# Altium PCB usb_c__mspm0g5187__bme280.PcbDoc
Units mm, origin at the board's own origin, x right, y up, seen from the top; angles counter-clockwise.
Board outline 64 x 33 mm, 2 copper layers (Top, Bottom), stack 0 mm thick; 27 components, 19 nets, 159 pads, 67 vias.
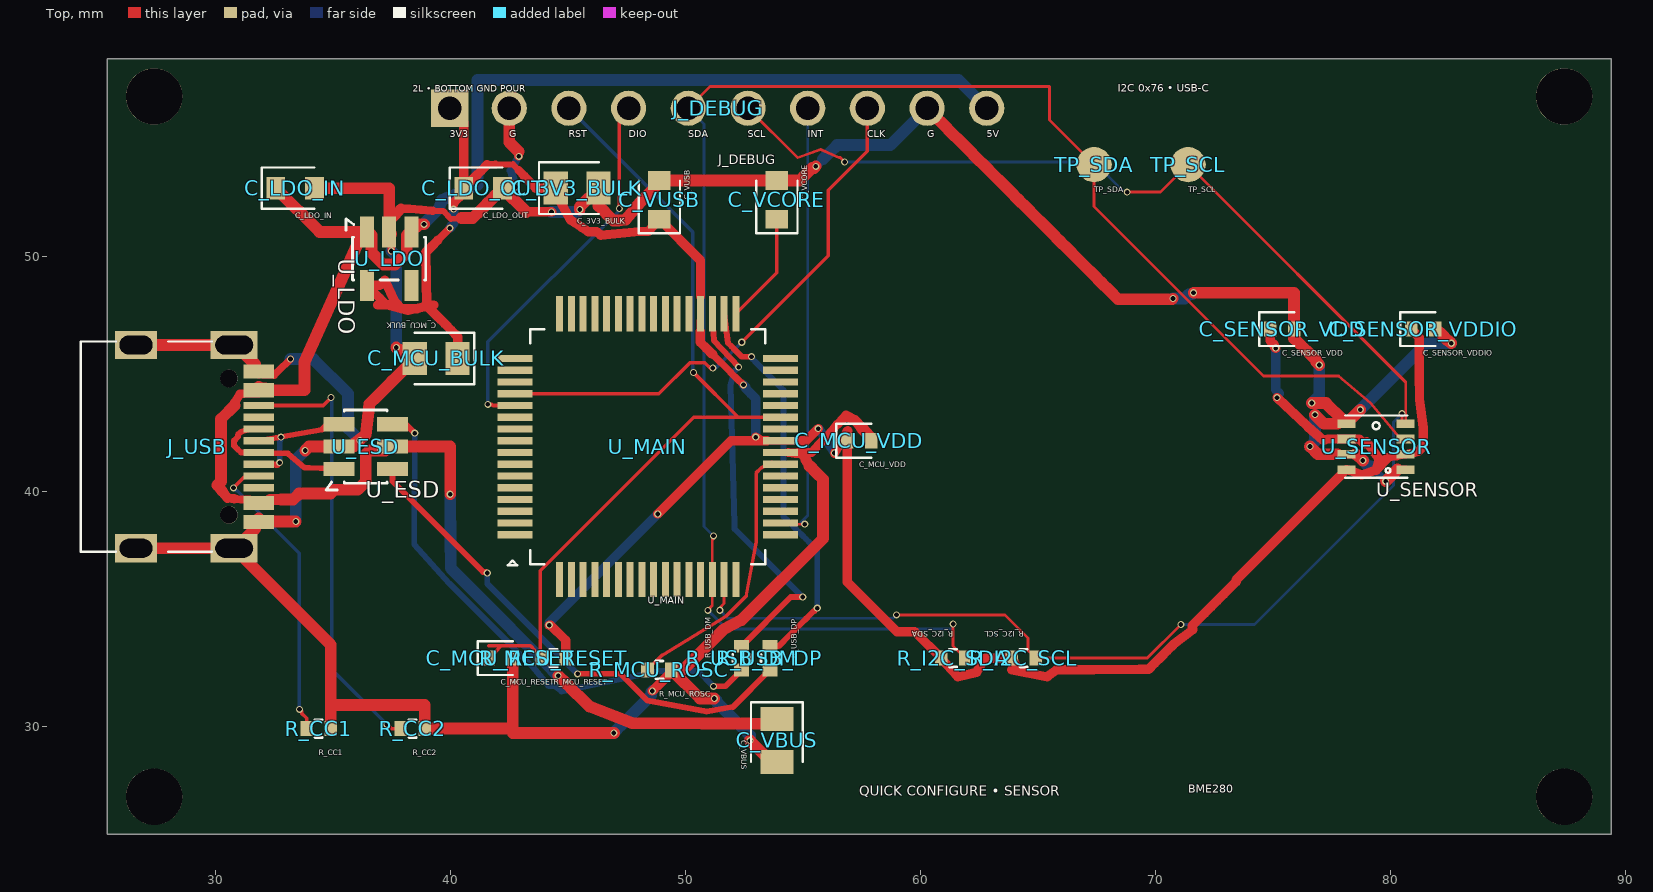
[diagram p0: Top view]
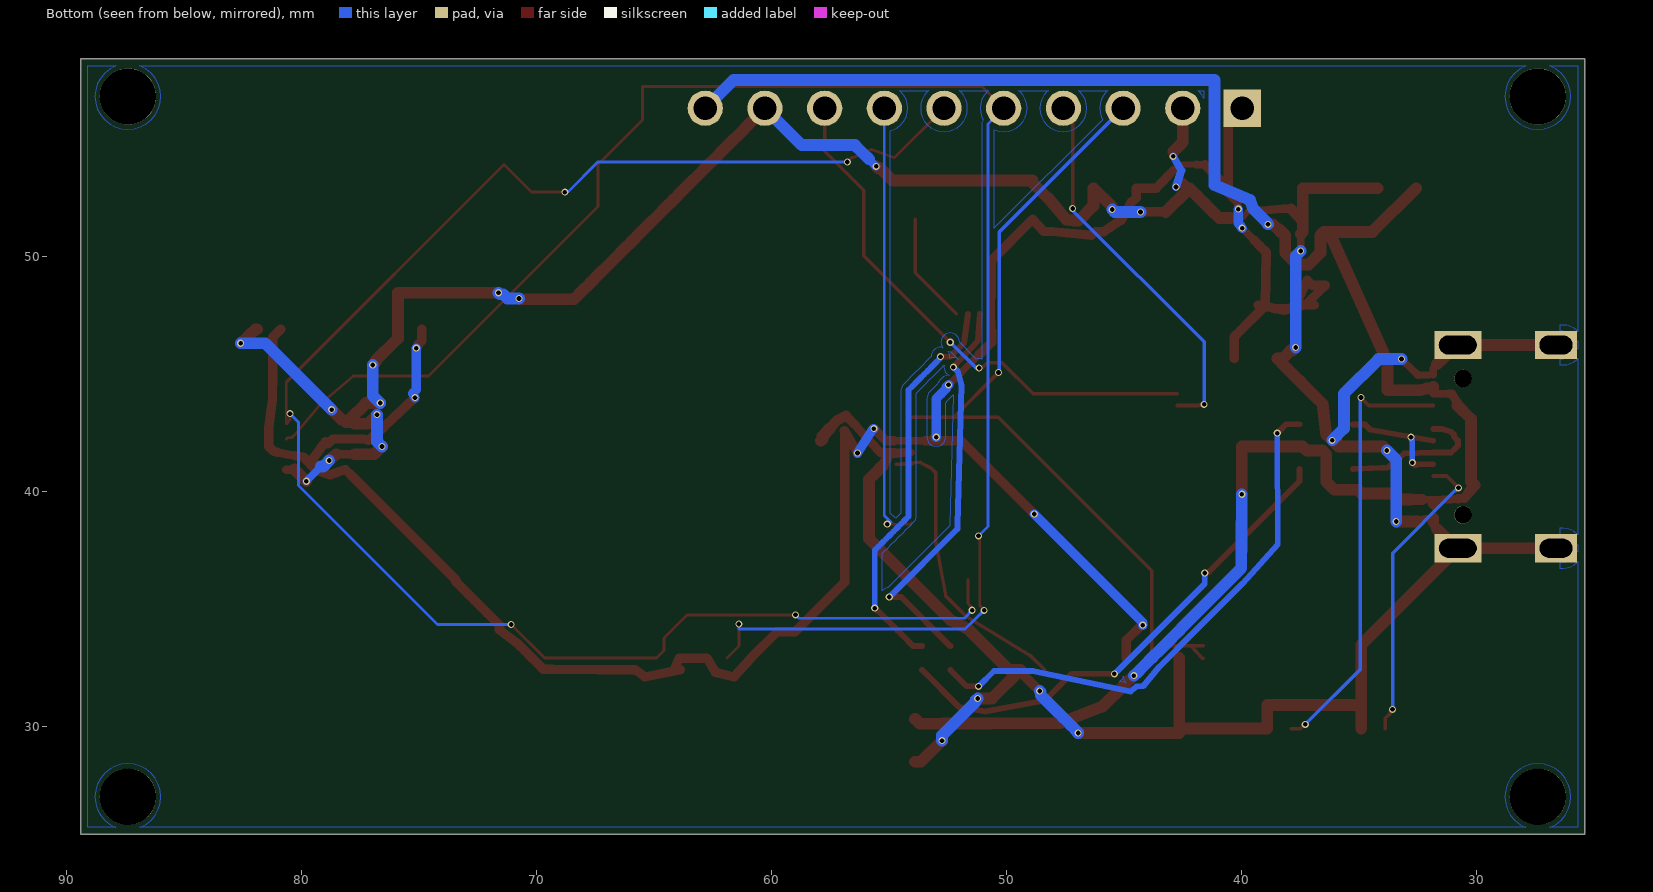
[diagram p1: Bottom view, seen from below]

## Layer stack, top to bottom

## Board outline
25.4,58.4 89.4,58.4 89.4,25.4 25.4,25.4

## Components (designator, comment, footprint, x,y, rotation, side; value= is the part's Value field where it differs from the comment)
C_3V3_BULK "" TSCIRCUIT-2.8500x1.4000mm 45.4,52.9 r0 top
C_LDO_IN "" TSCIRCUIT-2.4500x0.9500mm 33.4,52.9 r0 top
C_LDO_OUT "" TSCIRCUIT-2.4500x0.9500mm 41.4,52.9 r0 top
C_MCU_BULK "" TSCIRCUIT-2.8500x1.4000mm 39.4,45.65 r180 top
C_MCU_RESET "" TSCIRCUIT-1.5600x0.6400mm 42.15,32.9 r0 top
C_MCU_VDD "" TSCIRCUIT-1.5600x0.6400mm 57.4,42.15 r0 top
C_SENSOR_VDD "" TSCIRCUIT-1.5600x0.6400mm 75.4,46.9 r0 top
C_SENSOR_VDDIO "" TSCIRCUIT-1.5600x0.6400mm 81.4,46.9 r0 top
C_VBUS "" TSCIRCUIT-1.4000x2.8500mm 53.9,29.4 r270 top
C_VCORE "" TSCIRCUIT-0.9500x2.4500mm 53.9,52.4 r90 top
C_VUSB "" TSCIRCUIT-0.9500x2.4500mm 48.9,52.4 r90 top
J_DEBUG "" TSCIRCUIT-24.3600x1.5000mm 51.4,56.3 r0 top
J_USB "" TSCIRCUIT-6.7732x9.8502mm 29.112,41.9 r90 top
R_CC1 "" TSCIRCUIT-1.5600x0.6400mm 34.4,29.9 r0 top
R_CC2 "" TSCIRCUIT-1.5600x0.6400mm 38.4,29.9 r0 top
R_I2C_SCL "" TSCIRCUIT-1.5600x0.6400mm 64.4,32.9 r180 top
R_I2C_SDA "" TSCIRCUIT-1.5600x0.6400mm 61.4,32.9 r180 top
R_MCU_RESET "" TSCIRCUIT-1.5600x0.6400mm 44.4,32.9 r0 top
R_MCU_ROSC "" TSCIRCUIT-1.5600x0.6400mm 48.9,32.4 r0 top
R_USB_DM "" TSCIRCUIT-0.6400x1.5600mm 52.4,32.9 r90 top
R_USB_DP "" TSCIRCUIT-0.6400x1.5600mm 53.6,32.9 r90 top
TP_SCL "" TSCIRCUIT-1.5000x1.5000mm 71.4,53.9 r0 top
TP_SDA "" TSCIRCUIT-1.5000x1.5000mm 67.4,53.9 r0 top
U_ESD "" TSCIRCUIT-3.6000x2.5000mm 36.4,41.9 r0 top
U_LDO "" TSCIRCUIT-2.5000x3.6000mm 37.4,49.9 r270 top
U_MAIN "" TSCIRCUIT-12.8000x12.8000mm 48.4,41.9 r0 top
U_SENSOR "" TSCIRCUIT-3.2841x2.3142mm 79.4,41.9 r0 top

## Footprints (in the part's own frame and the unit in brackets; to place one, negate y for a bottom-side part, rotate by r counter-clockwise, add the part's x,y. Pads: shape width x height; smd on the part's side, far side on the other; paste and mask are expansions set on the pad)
TSCIRCUIT-0.6400x1.5600mm [mm]
  rect 0.54x0.64 smd: 1(-0.51,0) 2(0.51,0)
  silkscreen extent -0.15,-0.38 0.15,0.38
TSCIRCUIT-0.9500x2.4500mm [mm]
  rect 0.8x0.95 smd: 1(-0.825,0) 2(0.825,0)
  silkscreen extent -1.42,-0.88 0.82,0.87
TSCIRCUIT-1.4000x2.8500mm [mm]
  rect 1.025x1.4 smd: 1(-0.913,0) 2(0.913,0)
  silkscreen extent -1.63,-1.1 0.91,1.1
TSCIRCUIT-1.5000x1.5000mm [mm]
  round 1.5 smd: 1(0,0)
TSCIRCUIT-1.5600x0.6400mm [mm]
  rect 0.54x0.64 smd: 1(-0.51,0) 2(0.51,0)
  silkscreen extent -0.98,-0.72 0.51,0.72
TSCIRCUIT-2.4500x0.9500mm [mm]
  rect 0.8x0.95 smd: 1(-0.825,0) 2(0.825,0)
  silkscreen extent -1.42,-0.88 0.82,0.87
TSCIRCUIT-2.5000x3.6000mm [mm]
  rect 1.325x0.6 smd: 1(-1.138,-0.95) 2(-1.138,0) 3(-1.138,0.95) 4(1.137,0.95) 5(1.137,-0.95)
  silkscreen extent -1.69,-1.84 0.91,1.56
TSCIRCUIT-2.8500x1.4000mm [mm]
  rect 1.025x1.4 smd: 1(-0.913,0) 2(0.913,0)
  silkscreen extent -1.63,-1.1 0.91,1.1
TSCIRCUIT-3.2841x2.3142mm [mm]
  rect 0.767x0.364 smd: 1(1.259,-0.975) 2(1.259,-0.325) 3(1.259,0.325) 4(1.259,0.975) 5(-1.259,0.975) 6(-1.259,0.325) 7(-1.259,-0.325) 8(-1.259,-0.975)
  silkscreen extent -1.33,-1.33 1.33,1.33
TSCIRCUIT-3.6000x2.5000mm [mm]
  rect 1.325x0.6 smd: 1(-1.138,-0.95) 2(-1.138,0) 3(-1.138,0.95) 4(1.137,0.95) 5(1.137,0) 6(1.137,-0.95)
  silkscreen extent -1.69,-1.84 0.91,1.56
TSCIRCUIT-6.7732x9.8502mm [mm]
  rect 0.3x1.3 smd: 1(-3.35,-2.737) 2(-3.05,-2.737) 3(-2.55,-2.737) 4(-2.25,-2.737) 5(-1.75,-2.737) 6(-1.25,-2.737) 7(-0.75,-2.737) 8(-0.25,-2.737) 9(0.25,-2.737) 10(0.75,-2.737) 11(1.25,-2.737) 12(1.75,-2.737) 13(2.55,-2.737) 14(2.25,-2.737) 15(3.35,-2.737) 16(3.05,-2.737)
  rect 1.2x2 hole 0.8 slot 1.6 at 90 deg: 17(-4.325,-1.693) 18(4.325,-1.693)
  rect 1.2x1.8 hole 0.8 slot 1.4 at 90 deg: 19(4.325,2.487) 20(-4.325,2.487)
  round 0.75 hole 0.75 unplated: NPTH-1(-2.9,-1.468) NPTH-2(2.9,-1.468)
  silkscreen extent -4.47,-0.75 4.47,4.83
TSCIRCUIT-12.8000x12.8000mm [mm]
  rect 1.5x0.3 smd: 1(-5.65,-3.75) 2(-5.65,-3.25) 3(-5.65,-2.75) 4(-5.65,-2.25) 5(-5.65,-1.75) 6(-5.65,-1.25) 7(-5.65,-0.75) 8(-5.65,-0.25) 9(-5.65,0.25) 10(-5.65,0.75) 11(-5.65,1.25) 12(-5.65,1.75) 13(-5.65,2.25) 14(-5.65,2.75) 15(-5.65,3.25) 16(-5.65,3.75) 33(5.65,3.75) 34(5.65,3.25) 35(5.65,2.75) 36(5.65,2.25) 37(5.65,1.75) 38(5.65,1.25) 39(5.65,0.75) 40(5.65,0.25) 41(5.65,-0.25) 42(5.65,-0.75) 43(5.65,-1.25) 44(5.65,-1.75) 45(5.65,-2.25) 46(5.65,-2.75) 47(5.65,-3.25) 48(5.65,-3.75)
  rect 0.3x1.5 smd: 17(-3.75,5.65) 18(-3.25,5.65) 19(-2.75,5.65) 20(-2.25,5.65) 21(-1.75,5.65) 22(-1.25,5.65) 23(-0.75,5.65) 24(-0.25,5.65) 25(0.25,5.65) 26(0.75,5.65) 27(1.25,5.65) 28(1.75,5.65) 29(2.25,5.65) 30(2.75,5.65) 31(3.25,5.65) 32(3.75,5.65) 49(3.75,-5.65) 50(3.25,-5.65) 51(2.75,-5.65) 52(2.25,-5.65) 53(1.75,-5.65) 54(1.25,-5.65) 55(0.75,-5.65) 56(0.25,-5.65) 57(-0.25,-5.65) 58(-0.75,-5.65) 59(-1.25,-5.65) 60(-1.75,-5.65) 61(-2.25,-5.65) 62(-2.75,-5.65) 63(-3.25,-5.65) 64(-3.75,-5.65)
  silkscreen extent -5.95,-5.05 5,5
TSCIRCUIT-24.3600x1.5000mm [mm]
  rect 1.6x1.6 hole 1: 1(-11.43,0)
  round 1.5 hole 1: 2(-8.89,0) 3(-6.35,0) 4(-3.81,0) 5(-1.27,0) 6(1.27,0) 7(3.81,0) 8(6.35,0) 9(8.89,0) 10(11.43,0)

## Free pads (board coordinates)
  round 2.4 hole 2.4 unplated: NPTH-3(27.4,27) NPTH-4(87.4,27) NPTH-5(27.4,56.8) NPTH-6(87.4,56.8)

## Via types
v1: diameter 0.3, hole 0.2, Top to Bottom, 67 vias

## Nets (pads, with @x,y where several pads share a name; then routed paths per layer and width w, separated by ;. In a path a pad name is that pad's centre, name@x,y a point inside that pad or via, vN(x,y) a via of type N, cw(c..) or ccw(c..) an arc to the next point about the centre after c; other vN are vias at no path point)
".J_DEBUG > .pin4 to .U_MAIN > .pin12": J_DEBUG.4 U_MAIN.12 | length 16.2
  Top w0.15: v1(41.6,43.7) 41.771,43.7 41.821,43.65 U_MAIN.12 ; v1(47.194,52.033) 47.191,55.901 J_DEBUG.4
  Bottom w0.15: v1(41.6,43.7) 41.6,46.359 47.143,51.902 v1(47.194,52.033)
".J_DEBUG > .pin8 to .U_MAIN > .pin13": J_DEBUG.8 U_MAIN.13 | length 22.9
  Top w0.15: U_MAIN.13 48.874,44.15 50.201,45.476 50.837,45.476 51.093,45.22 51.147,45.22 v1(51.173,45.246) ; v1(52.405,46.342) 56.086,50.023 56.086,52.803 57.75,54.467 J_DEBUG.8
  Bottom w0.15: v1(51.173,45.246) 51.301,45.246 52.27,46.215 52.278,46.215 v1(52.405,46.342)
".U_MAIN > .pin42 to .R_MCU_ROSC > .pin1": R_MCU_ROSC.1 U_MAIN.42 | length 13.1
  Top w0.15: R_MCU_ROSC.1 49.008,33.018 51.747,34.693 52.585,35.531 53.013,37.85 53.013,40.775 53.238,41 53.687,41.225 54.709,41.15 U_MAIN.42
GND: C_3V3_BULK.2 C_LDO_IN.2 C_LDO_OUT.2 C_MCU_BULK.2 C_MCU_RESET.2 C_MCU_VDD.2 C_SENSOR_VDD.2 C_SENSOR_VDDIO.2 C_VBUS.2 C_VCORE.2 C_VUSB.2 J_DEBUG.2 J_DEBUG.9 J_USB.1 J_USB.2 J_USB.15 J_USB.16 J_USB.17 J_USB.18 J_USB.19 J_USB.20 R_CC1.2 R_CC2.2 R_MCU_ROSC.2 U_ESD.2 U_LDO.2 U_MAIN.41 U_SENSOR.1 U_SENSOR.5 U_SENSOR.7 | length 174.2
  Top w0.25: 39.242,51.934 39.697,51.934 40.025,51.587 40.478,51.628
  Top w0.3: J_USB.1@31.699,38.4 J_USB.1 J_USB.1@31.849,38.7 ; 31.699,45.4 J_USB.15 J_USB.16@31.849,45.1 ; J_USB.2 31.945,38.839 32.037,38.85 32.13,38.85 32.224,38.85 32.36,38.714 J_USB.2@32.499,38.714 ; J_USB.16 31.945,44.961 32.037,44.95 32.13,44.95 32.224,44.95 32.318,44.95 32.412,44.95 32.499,44.95 ; U_MAIN.41@54.385,41.65 U_MAIN.41 54.144,41.65 54.237,41.65 54.331,41.65 54.425,41.65 54.519,41.65 54.612,41.65 54.706,41.65 U_MAIN.41@54.8,41.65
  Top w0.31: J_USB.16 J_USB.16@31.849,45.1
  Top w0.312: 32.505,44.95 32.791,45.224 33.076,45.497 v1(33.203,45.625) ; v1(37.493,50.224) 37.493,50.584 U_LDO.2@37.493,50.944
  Top w0.325: 32.499,44.95 32.505,44.95 ; C_LDO_OUT.2 42.5,53.175 v1(42.8,52.95)
  Top w0.364: U_SENSOR.7@77.758,41.575 U_SENSOR.7 U_SENSOR.7@78.525,41.575 ; U_SENSOR.5@77.758,42.875 U_SENSOR.5 ; 77.959,43.057 U_SENSOR.5 ; 78.323,43.057 U_SENSOR.5 ; U_SENSOR.1@80.306,40.925 U_SENSOR.1
  Top w0.375: 37.9,52.025 38.275,52.025 38.759,51.979 39.242,51.934 ; 42.903,54.463 42.903,54.269 v1(42.917,54.255) ; U_MAIN.41@54.8,41.65 55.093,41.652 55.385,41.654 55.714,42.005 56.042,42.356 56.252,42.597 56.463,42.837 56.65,43.025
  Top w0.4: 43.236,51.889 43.592,51.889 43.949,51.889 44.306,51.889 v1(44.312,51.883) ; v1(48.6,31.5) 49.41,32.31 R_MCU_ROSC.2 ; U_MAIN.41@54.385,41.65 54.682,41.619 54.978,41.587 55.135,41.333 ; 56.65,43.025 56.838,43.212
  Top w0.437: 37.65,51.74 37.9,52.025 ; 56.838,43.212 57.212,43.025 57.525,42.681
  Top w0.45: U_LDO.2@37.4,51.455 37.65,51.74 ; 55.135,41.333 55.291,41.079 ; v1@70.723,48.174 v1(70.755,48.206)
  Top w0.475: v1(71.632,48.448) 72.087,48.448 72.542,48.448
  Top w0.5: J_USB.20 J_USB.17 ; J_USB.19 J_USB.18 ; J_USB.18 30.874,46.225 31.474,45.625 31.699,45.4 ; J_USB.1@31.699,38.4 31.474,38.175 30.874,37.575 J_USB.17 34.91,33.471 R_CC1.2 34.91,30.9 38.91,30.9 R_CC2.2 42.66,29.9 C_MCU_RESET.2 42.66,29.716 v1(46.963,29.716) ; J_USB.1@31.849,38.7 J_USB.2 ; 32.499,38.714 v1(33.429,38.714) ; v1(33.825,41.737) 33.988,41.9 U_ESD.2 ; C_LDO_IN.2 37.4,52.9 U_LDO.2 ; v1(36.152,42.169) 35.882,41.9 U_ESD.2 ; U_LDO.2@37.4,51.455 U_LDO.2 ; U_LDO.2@37.493,50.945 U_LDO.2 ; v1(37.705,46.115) 37.803,46.017 37.889,46.017 38.073,45.833 38.256,45.65 C_MCU_BULK.2 38.167,45.329 37.846,45.009 37.526,44.688 37.205,44.367 36.884,44.047 36.564,43.726 36.4,42.4 35.737,41.9 U_ESD.2 ; 40.478,51.628 40.953,51.628 41.271,51.946 41.589,52.264 41.907,52.582 C_LDO_OUT.2 42.562,52.563 42.899,52.226 43.236,51.889 ; J_DEBUG.2 42.51,55.818 42.51,55.337 42.51,54.855 42.706,54.659 42.903,54.463 ; v1(45.515,51.991) 45.515,52.102 C_3V3_BULK.2 46.313,52.144 46.9,51.556 46.931,51.525 47.15,51.525 47.463,51.556 47.716,51.857 47.97,52.157 48.224,52.458 48.565,52.794 48.906,53.129 C_VUSB.2 C_VCORE.2 54.382,53.225 54.864,53.225 55.132,53.493 55.4,53.761 55.491,53.761 v1(55.557,53.827) ; v1(51.238,31.181) 50.629,31.181 R_MCU_ROSC.2 49.916,32.4 51.636,34.12 52.4,34.525 55.862,37.987 55.862,40.508 55.577,40.794 55.291,41.079 ; v1(52.751,29.389) 52.767,29.373 53.652,28.487 C_VBUS.2 ; 57.525,42.681 57.837,42.337 57.837,42.222 C_MCU_VDD.2 ; J_DEBUG.9 60.643,55.947 60.997,55.593 61.35,55.24 61.703,54.887 62.057,54.533 62.41,54.18 62.763,53.827 63.117,53.473 63.47,53.12 63.823,52.767 64.176,52.414 64.53,52.06 64.883,51.707 65.236,51.354 65.59,51 65.943,50.647 66.296,50.294 66.65,49.94 67.003,49.587 67.356,49.234 67.71,48.88 68.063,48.527 68.416,48.174 68.856,48.174 69.296,48.174 69.736,48.174 70.176,48.174 70.616,48.174 v1@70.723,48.174 ; 72.542,48.448 75.91,48.448 C_SENSOR_VDD.2 75.91,46.501 76.865,45.546 76.865,45.49 v1(76.979,45.376) ; v1(76.588,41.904) 76.918,41.575 77.758,41.575 ; v1(76.66,43.754) 77.262,43.754 77.959,43.057 ; v1(76.795,43.26) 77.18,42.875 77.758,42.875 ; 78.323,43.057 78.727,43.461 v1(78.727,43.474) ; 78.525,41.575 78.54,41.575 v1(78.837,41.309) ; v1(79.807,40.426) U_SENSOR.1@80.306,40.925 ; C_SENSOR_VDDIO.2 81.964,46.9 82.21,46.654 82.456,46.408 82.492,46.408 v1(82.6,46.3)
  Bottom w0.312: 42.577,53.647 42.747,53.951 v1(42.917,54.255)
  Bottom w0.325: 79.185,41.047 v1(79.807,40.426)
  Bottom w0.35: 42.577,53.647 v1(42.8,52.95) ; v1(55.557,53.827) 55.858,54.128
  Bottom w0.5: v1(33.203,45.625) 34.175,45.625 35.65,44.15 35.65,42.671 v1(36.152,42.169) ; v1(33.429,38.714) 33.429,41.341 v1(33.825,41.737) ; v1(37.493,50.224) 37.705,50.012 v1(37.705,46.115) ; v1(44.312,51.883) 45.407,51.883 v1(45.515,51.991) ; v1(46.963,29.716) 46.97,29.739 47.287,30.056 47.604,30.373 47.921,30.69 48.238,31.007 48.555,31.324 48.555,31.455 v1(48.6,31.5) ; v1(51.238,31.181) 51.324,31.095 51.324,31.047 52.751,29.62 v1(52.751,29.389) ; 55.858,54.128 56.16,54.43 56.461,54.731 58.721,54.731 J_DEBUG.9 ; v1(70.755,48.206) 71.255,48.206 71.431,48.382 71.566,48.382 v1(71.632,48.448) ; v1(76.588,41.904) 76.795,42.111 v1(76.795,43.26) ; v1(76.66,43.754) 76.979,44.073 v1(76.979,45.376) ; v1(78.727,43.474) 81.553,46.3 v1(82.6,46.3) ; v1(78.837,41.309) 79.095,41.051 79.185,41.051 79.185,41.047
MAIN_RESET: C_MCU_RESET.1 J_DEBUG.3 R_MCU_RESET.1 U_MAIN.38 | length 38.4
  Top w0.15: C_MCU_RESET.1 41.68,32.9 42.16,33.425 41.64,33.425 43.2,33.425 43.16,33.425 43.41,33.425 R_MCU_RESET.1 43.821,32.962 43.824,36.624 50.354,43.15 U_MAIN.38 52.256,43.15 v1(50.352,45.054)
  Bottom w0.15: J_DEBUG.3 50.319,51.031 50.319,45.233 50.319,45.087 v1(50.352,45.054)
MSP_VCORE: C_VCORE.1 U_MAIN.32 | length 4.7
  Top w0.15: U_MAIN.32 53.9,49.3 C_VCORE.1
SENSOR_INT: J_DEBUG.7 U_MAIN.47 | length 19
  Top w0.12: U_MAIN.47 54.1,38.6 v1(55.084,38.6)
  Bottom w0.12: v1(55.084,38.6) 55.005,38.679 54.925,38.679 55.21,38.964 J_DEBUG.7
SENSOR_SCL: J_DEBUG.6 R_I2C_SCL.1 TP_SCL.1 U_MAIN.50 U_SENSOR.4 | length 73.7
  Top w0.12: v1(51.473,34.937) 51.496,34.983 51.496,35.064 51.65,35.218 U_MAIN.50 ; J_DEBUG.6 54.773,54.197 55.76,54.542 56.549,54.197 56.598,54.197 v1(56.786,54.009) ; v1(58.989,34.741) 63.6,34.741 64.58,33.761 64.58,33.23 R_I2C_SCL.1 69.659,32.9 71.074,34.315 v1(71.087,34.328) ; v1(68.805,52.729) 70.229,52.729 TP_SCL.1 80.659,44.641 U_SENSOR.4 80.5,43.034 v1(80.5,43.3)
  Bottom w0.12: v1(51.473,34.937) 51.789,34.598 58.726,34.598 58.846,34.598 v1(58.989,34.741) ; v1(56.786,54.009) 67.406,54.009 68.653,52.762 68.772,52.762 v1(68.805,52.729) ; v1(71.087,34.328) 74.218,34.328 80.138,40.245 80.135,42.935 80.496,43.296 v1(80.5,43.3)
SENSOR_SDA: J_DEBUG.5 R_I2C_SDA.1 TP_SDA.1 U_MAIN.51 U_SENSOR.3 | length 73.6
  Top w0.12: J_DEBUG.5 51.055,57.225 65.497,57.225 65.497,55.803 TP_SDA.1 67.4,52.114 74.609,44.905 77.807,44.905 79.162,43.757 80.269,42.444 80.433,42.28 80.604,42.28 U_SENSOR.3 ; v1(50.959,34.934) 51.05,35.002 51.05,35.042 51.15,35.142 U_MAIN.51 51.15,37.929 51.2,37.979 v1(51.2,38.103) ; v1(61.4,34.35) 61.4,33.41 R_I2C_SDA.1
  Bottom w0.12: J_DEBUG.5 50.8,55.63 50.8,55.578 50.8,38.503 v1(51.2,38.103) ; v1(50.959,34.934) 51.773,34.143 61.4,34.143 v1(61.4,34.35)
usb-dm-mcu: R_USB_DM.2 U_MAIN.30 | length 17.2
  Top w0.25: U_MAIN.30 51.219,46.414 v1(52.274,45.283) ; R_USB_DM.2 54.49,35.5 v1(55,35.5)
  Bottom w0.25: v1(52.274,45.283) 52.083,45.107 51.93,44.514 52.097,38.569 52.098,38.4 54.983,35.515 54.985,35.515 v1(55,35.5)
usb-dm-phy: R_USB_DM.1 U_ESD.4 | length 23.1
  Top w0.25: U_ESD.4 38.113,42.85 38.388,42.575 v1(38.488,42.475) ; v1(51.2,31.7) 51.71,31.7 R_USB_DM.1
  Bottom w0.25: v1(38.488,42.475) 38.47,37.728 39.956,36.082 42.036,34.002 43.52,32.514 44.2,31.7 44.478,31.689 44.726,31.484 48.895,32.355 50.545,32.355 51.194,31.706 v1(51.2,31.7)
usb-dm-port: J_USB.7 J_USB.9 U_ESD.3 | length 6.6
  Top w0.25: J_USB.7 32.086,41.15 32.322,41.15 32.559,41.15 32.587,41.122 32.647,41.122 v1(32.741,41.216) ; v1(32.8,42.3) J_USB.9 34.531,42.616 34.764,42.849 U_ESD.3
  Bottom w0.25: v1(32.741,41.216) 32.741,41.451 32.741,41.686 32.741,41.922 32.741,42.157 32.782,42.198 32.782,42.282 v1(32.8,42.3)
usb-dp-mcu: R_USB_DP.2 U_MAIN.31 | length 17
  Top w0.25: U_MAIN.31 51.818,46.312 51.965,46.166 52.112,46.019 52.258,45.873 52.405,45.726 52.614,45.726 v1(52.823,45.726) ; R_USB_DP.2 53.788,33.41 53.976,33.41 54.143,33.577 54.309,33.744 54.476,33.911 54.643,34.078 54.81,34.244 54.977,34.411 55.144,34.578 55.311,34.745 55.478,34.912 55.504,34.912 v1(55.616,35.024)
  Bottom w0.25: v1(52.823,45.726) 52.858,45.691 52.858,45.629 53.023,45.464 53.188,45.299 53.353,45.134 53.518,44.969 53.683,44.804 53.848,44.639 54.013,44.474 54.178,44.309 54.178,44.064 54.178,43.82 54.178,43.575 54.178,43.33 54.178,43.086 54.178,42.841 54.178,42.596 54.178,42.352 54.178,42.107 54.178,41.863 54.178,41.618 54.178,41.373 54.178,41.129 54.178,40.884 54.178,40.64 54.178,40.395 54.178,40.15 54.178,39.906 54.178,39.661 54.178,39.416 54.178,39.172 54.178,38.927 54.338,38.767 54.497,38.608 54.657,38.448 54.817,38.288 54.977,38.128 55.137,37.968 55.296,37.809 55.456,37.649 55.616,37.489 55.616,37.243 55.616,36.996 55.616,36.75 55.616,36.503 55.616,36.257 55.616,36.01 55.616,35.764 55.616,35.517 55.616,35.271 v1(55.616,35.024)
usb-dp-phy: R_USB_DP.1 U_ESD.6 | length 21.4
  Top w0.25: U_ESD.6 37.537,40.427 41.396,36.569 41.524,36.569 v1(41.574,36.519) ; v1(45.422,32.232) 47.241,32.232 48.386,31.094 50.909,30.624 52.037,30.827 R_USB_DP.1
  Bottom w0.25: v1(41.574,36.519) 41.574,36.061 45.314,32.321 45.333,32.321 v1(45.422,32.232)
usb-dp-port: J_USB.8 J_USB.10 U_ESD.1 | length 6.3
  Top w0.25: J_USB.10 31.666,42.65 31.483,42.65 31.087,42.525 30.963,42.4 30.97,42.32 30.804,42.155 30.804,41.937 30.948,41.793 31.091,41.65 31.28,41.65 31.47,41.65 31.659,41.65 J_USB.8 33.1,41.6 33.796,41.004 34,41 U_ESD.1
USB_CC1: J_USB.6 R_CC1.1 | length 12.8
  Top w0.15: v1(30.773,40.145) 31.278,40.65 J_USB.6 ; v1(33.58,30.719) 33.671,30.628 33.671,30.559 33.89,30.34 R_CC1.1
  Bottom w0.15: v1(30.773,40.145) 30.902,40.015 30.929,40.015 33.58,37.365 v1(33.58,30.719)
USB_CC2: J_USB.12 R_CC2.1 | length 18.8
  Top w0.15: J_USB.12 34.588,43.65 v1(34.928,43.99) ; v1(37.296,30.08) 37.394,29.982 37.424,29.982 37.506,29.9 R_CC2.1
  Bottom w0.15: v1(34.928,43.99) 34.948,43.97 34.948,43.856 34.948,32.428 v1(37.296,30.08)
VBUS5: C_LDO_IN.1 C_VBUS.1 J_DEBUG.10 J_USB.3 J_USB.4 J_USB.13 J_USB.14 U_ESD.5 U_LDO.1 U_LDO.3 | length 87.6
  Top w0.275: J_USB.3 J_USB.3@31.849,39.5
  Top w0.3: J_USB.14@31.199,44.15 31.453,44.15 J_USB.14 J_USB.14@31.849,44.3 ; J_USB.4@31.465,39.65 J_USB.4 ; J_USB.3@31.849,39.5 J_USB.4 ; J_USB.4@32.329,39.65 J_USB.4
  Top w0.35: 30.803,39.681 31.08,39.65 J_USB.4@31.465,39.65
  Top w0.375: 30.822,43.654 30.822,43.785 31.056,44.15 31.199,44.15
  Top w0.4: 30.525,39.713 30.803,39.681
  Top w0.425: 30.305,39.987 30.525,39.713
  Top w0.475: 30.085,40.261 30.305,39.987 ; J_USB.13@31.849,44.3 J_USB.13 J_USB.13@32.125,44.375 ; J_USB.4@32.329,39.65 32.81,39.65
  Top w0.5: 30.085,40.261 30.243,40.419 30.243,43.075 30.822,43.654 ; J_USB.13@32.125,44.375 32.4,44.3 33.8,44.3 33.8,45.5 36.134,50.722 U_LDO.1 ; C_LDO_IN.1 34.438,51.038 U_LDO.1 ; 32.81,39.65 33.29,39.65 33.317,39.65 33.567,39.9 34.9,39.9 35.067,40.067 36.067,40.067 36.4,40.4 36.4,41.567 36.567,41.733 37.233,41.733 37.4,41.9 U_ESD.5 39.998,41.9 v1(39.998,39.873) ; v1(38.885,51.362) 38.675,51.362 U_LDO.3 38.4,51.088 38.4,51.15 38.15,50.9 38.15,50.15 37.65,49.65 37.15,49.65 36.65,50.15 36.65,50.9 36.512,51.038 U_LDO.1 ; v1(44.594,32.152) 44.927,31.822 45.261,31.493 45.594,31.163 45.928,30.834 47.733,30.135 48.23,30.133 48.727,30.131 49.224,30.129 49.722,30.126 50.219,30.124 50.716,30.122 51.214,30.12 51.711,30.118 52.208,30.116 52.706,30.114 53.203,30.112 53.7,30.11 C_VBUS.1
  Bottom w0.5: v1(38.885,51.362) 38.909,51.386 38.909,51.425 39.216,51.732 39.524,52.04 39.65,52.4 41.161,53.025 41.161,57.504 43.759,57.504 48.619,57.504 53.171,57.504 61.626,57.504 J_DEBUG.10 ; v1(39.998,39.873) 40.001,39.424 40.004,38.975 40.007,38.526 40.011,38.077 40.014,37.628 40.017,37.179 40.02,36.73 40.364,36.384 40.707,36.039 41.051,35.694 41.394,35.348 41.738,35.003 42.081,34.658 42.425,34.312 42.769,33.967 43.112,33.622 43.456,33.276 43.799,32.931 44.143,32.586 44.487,32.24 v1(44.594,32.152)
VCC_3V3: C_3V3_BULK.1 C_LDO_OUT.1 C_MCU_BULK.1 C_MCU_VDD.1 C_SENSOR_VDD.1 C_SENSOR_VDDIO.1 C_VUSB.1 J_DEBUG.1 R_I2C_SCL.2 R_I2C_SDA.2 R_MCU_RESET.2 U_LDO.5 U_MAIN.29 U_MAIN.40 U_SENSOR.2 U_SENSOR.6 U_SENSOR.8 | length 116
  Top w0.262: 41.93,53.9 42.296,53.909 42.663,53.918 42.906,53.664
  Top w0.3: v1(40.146,52.006) 40.194,52.328 ; U_MAIN.29@50.647,47.248 U_MAIN.29 50.65,47.65 50.65,47.75 50.65,47.85 50.65,47.95 50.65,48.05 50.65,48.15 50.65,48.25 50.65,48.3 ; 51.424,45.567 51.687,45.308 51.949,45.049 51.925,45.05 52.2,44.791 ; 53.3,42.15 53.35,42.15 53.45,42.15 53.55,42.15 53.65,42.15 53.75,42.15 53.85,42.15 53.95,42.15 U_MAIN.40 ; U_MAIN.40@53.479,42.15 53.765,42.15 U_MAIN.40 ; U_MAIN.40@54.8,42.15 54.75,42.15 54.65,42.15 54.55,42.15 54.45,42.15 54.35,42.15 54.25,42.15 54.15,42.15 U_MAIN.40
  Top w0.312: 51.162,45.826 51.424,45.567 ; 52.2,44.791 v1(52.474,44.531)
  Top w0.316: U_MAIN.29@50.642,46.8 50.643,46.947 U_MAIN.29@50.647,47.248
  Top w0.325: 39.468,50.68 39.726,50.938 v1(39.984,51.196)
  Top w0.337: 41.563,53.891 41.93,53.9
  Top w0.363: 42.906,53.664 43.15,53.41
  Top w0.364: U_SENSOR.6@77.758,42.225 77.841,42.225 77.941,42.225 78.041,42.225 U_SENSOR.6 78.412,42.225 U_SENSOR.6@78.525,42.225 ; U_SENSOR.8@77.959,40.743 U_SENSOR.8 U_SENSOR.8@78.525,40.794 ; U_SENSOR.2@80.275,41.512 U_SENSOR.2 U_SENSOR.2@81.042,41.664
  Top w0.4: U_LDO.5 36.723,48.762 36.996,48.762 37.217,48.983 37.667,48.033 37.933,47.767 38.6,47.767 39,47.9 38.951,50.163 39.21,50.422 39.468,50.68 ; U_LDO.5 36.724,48.488 36.998,48.214 37.272,47.94 37.614,47.94 37.263,47.93 36.916,47.925 37.313,47.925 38.2,47.7 39.301,47.925 38.957,47.94 39.228,47.669 39.499,47.398 39.77,47.126 40.041,46.855 40.313,46.584 40.313,46.273 40.313,45.961 C_MCU_BULK.1 ; J_DEBUG.1 40.575,55.695 C_LDO_OUT.1 ; 40.194,52.328 40.384,52.518 40.575,52.709 C_LDO_OUT.1 ; 41.563,53.891 41.316,53.643 41.069,53.395 40.822,53.148 C_LDO_OUT.1 ; 43.15,53.41 43.393,53.156 43.637,52.902 43.92,52.901 44.204,52.901 C_3V3_BULK.1 44.483,52.69 44.479,52.479 44.7,52.3 45.095,51.572 45.353,51.397 45.611,51.222 45.869,51.046 46.234,51.047 46.4,50.9 48.057,51.053 48.421,51.054 48.661,51.314 C_VUSB.1 50.65,49.825 50.65,48.35 50.65,48.3 ; v1(44.212,34.3) 44.266,34.3 44.91,33.656 R_MCU_RESET.2 ; v1(48.829,39.031) 51.948,42.15 53.25,42.15 53.3,42.15 ; 50.642,46.8 50.64,46.645 50.637,46.344 50.899,46.085 51.162,45.826 ; v1(53,42.3) 53.048,42.252 53.092,42.252 53.194,42.15 U_MAIN.40@53.479,42.15 ; 54.8,42.15 54.85,42.15 55.14,42.15 v1(55.656,42.666) ; v1(56.35,41.625) 56.911,42.577 56.898,42.555 C_MCU_VDD.1 56.89,36.14 59.01,34.02 59.77,34.02 R_I2C_SDA.2 61.6,32.1 62.4,32.3 62.764,32.9 63.139,32.9 63.515,32.9 R_I2C_SCL.2 63.94,32.9 64.155,32.413 63.89,32.405 65.4,32.1 65.81,32.406 66.2,32.408 66.591,32.409 66.981,32.41 67.371,32.412 67.761,32.413 68.152,32.415 68.542,32.416 68.932,32.417 69.323,32.419 69.713,32.42 69.979,32.686 70.246,32.953 70.512,33.219 70.778,33.485 71.6,34.1 71.577,34.284 71.843,34.55 72.11,34.817 72.376,35.083 72.642,35.349 72.908,35.615 73.175,35.882 73.441,36.148 73.441,36.225 73.717,36.501 73.994,36.778 74.27,37.054 74.547,37.331 74.823,37.607 75.1,37.884 75.376,38.16 75.653,38.437 75.929,38.713 76.206,38.99 76.482,39.266 76.759,39.543 77.035,39.819 77.312,40.096 77.588,40.372 77.865,40.648 U_SENSOR.8@77.959,40.743 ; C_SENSOR_VDD.1 74.89,46.408 75.072,46.226 75.072,46.149 v1(75.129,46.092) ; v1(75.181,43.982) 76.488,42.747 77.152,42.17 77.341,42.225 77.441,42.225 77.541,42.225 77.641,42.225 77.741,42.225 77.758,42.225 ; U_SENSOR.8 78.467,40.812 78.792,40.699 79.4,40.9 ; 78.525,40.794 78.8,40.7 79.4,40.9 ; 78.525,42.225 78.683,42.225 78.897,42.012 79,42.1 79.536,41.372 79.4,40.9 ; 80.275,41.512 80.2,41.5 79.933,41.46 79.4,40.9 ; C_SENSOR_VDDIO.1 81.059,46.731 81.229,46.561 81.231,46.182 81.234,45.803 81.237,45.424 81.239,45.045 81.242,44.666 81.244,44.287 81.247,43.908 81.4,42.7 81.4,41.9 81.2,41.7 81.042,41.664
  Bottom w0.4: v1(39.984,51.196) 40.045,51.257 40.045,51.299 40.146,51.4 40.146,51.703 v1(40.146,52.006) ; v1(44.212,34.3) 44.2,34.403 v1@48.722,38.926 ; v1@48.724,38.926 v1(48.829,39.031) ; v1(52.474,44.531) 52.571,44.436 52.571,44.371 52.786,44.157 53,43.942 53,43.614 53,43.285 53,42.957 53,42.628 v1(53,42.3) ; v1(55.656,42.666) 55.661,42.661 55.678,42.661 55.707,42.632 v1(56.35,41.625) ; v1(75.129,46.092) 75.129,44.316 75.286,44.159 v1(75.181,43.982)
pads on no net: J_USB.5 J_USB.11 J_USB.NPTH-1 J_USB.NPTH-2 U_LDO.4 U_MAIN.1 U_MAIN.2 U_MAIN.3 U_MAIN.4 U_MAIN.5 U_MAIN.6 U_MAIN.7 U_MAIN.8 U_MAIN.9 U_MAIN.10 U_MAIN.11 U_MAIN.14 U_MAIN.15 U_MAIN.16 U_MAIN.17 U_MAIN.18 U_MAIN.19 U_MAIN.20 U_MAIN.21 U_MAIN.22 U_MAIN.23 U_MAIN.24 U_MAIN.25 U_MAIN.26 U_MAIN.27 U_MAIN.28 U_MAIN.33 U_MAIN.34 U_MAIN.35 U_MAIN.36 U_MAIN.37 U_MAIN.39 U_MAIN.43 U_MAIN.44 U_MAIN.45 U_MAIN.46 U_MAIN.48 U_MAIN.49 U_MAIN.52 U_MAIN.53 U_MAIN.54 U_MAIN.55 U_MAIN.56 U_MAIN.57 U_MAIN.58 U_MAIN.59 U_MAIN.60 U_MAIN.61 U_MAIN.62 U_MAIN.63 U_MAIN.64

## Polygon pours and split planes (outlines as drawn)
GND on Bottom (solid): 197 vertices, not listed, extent 25.7,25.7 89.1,58.1
GND on Bottom (solid): 41.86,57.054 41.611,57.054 41.611,56.729 41.679,56.856 41.803,57.007
GND on Bottom (solid): 46.94,57.054 45.7,57.054 45.757,57.007 45.881,56.856 45.974,56.683 46.031,56.495 46.05,56.3 46.031,56.105 45.974,55.917 45.921,55.818 50.514,51.225 50.54,51.193 50.54,55.391 50.513,55.376 50.325,55.319 50.13,55.3 49.935,55.319 49.747,55.376 49.574,55.469 49.423,55.593 49.299,55.744 49.206,55.917 49.149,56.105 49.13,56.3 49.149,56.495 49.206,56.683 49.299,56.856 49.423,57.007 49.48,57.054 48.619,57.054 48.24,57.054 48.297,57.007 48.421,56.856 48.514,56.683 48.571,56.495 48.59,56.3 48.571,56.105 48.514,55.917 48.421,55.744 48.297,55.593 48.146,55.469 47.973,55.376 47.785,55.319 47.59,55.3 47.395,55.319 47.207,55.376 47.034,55.469 46.883,55.593 46.759,55.744 46.666,55.917 46.609,56.105 46.59,56.3 46.609,56.495 46.666,56.683 46.759,56.856 46.883,57.007
GND on Bottom (solid): 52.494,45.953 52.483,45.95 52.405,45.942 52.388,45.944 52.069,45.625 52.121,45.653 52.196,45.676 52.274,45.683 52.352,45.676 52.427,45.653 52.43,45.651 52.423,45.726 52.431,45.804 52.453,45.879 52.49,45.948
GND on Bottom (solid): 52.02,57.054 50.78,57.054 50.837,57.007 50.961,56.856 51.054,56.683 51.111,56.495 51.13,56.3 51.111,56.105 51.054,55.917 50.993,55.803 51.016,55.774 51.04,55.729 51.055,55.681 51.06,55.63 51.06,55.578 51.06,45.628 51.095,45.638 51.173,45.646 51.251,45.638 51.292,45.626 52.005,46.339 52.005,46.342 52.013,46.42 52.035,46.495 52.072,46.564 52.122,46.625 52.183,46.675 52.252,46.712 52.327,46.734 52.405,46.742 52.483,46.734 52.558,46.712 52.627,46.675 52.688,46.625 52.738,46.564 52.775,46.495 52.797,46.42 52.805,46.342 52.797,46.264 52.775,46.189 52.738,46.12 52.734,46.115 52.745,46.118 52.823,46.126 52.901,46.118 52.976,46.096 53.045,46.059 53.106,46.009 53.156,45.948 53.193,45.879 53.215,45.804 53.223,45.726 53.223,45.723 53.253,45.694 53.418,45.529 53.583,45.364 53.748,45.199 53.913,45.034 54.078,44.869 54.243,44.704 54.408,44.539 54.448,44.489 54.478,44.433 54.497,44.372 54.503,44.309 54.503,44.064 54.503,43.82 54.503,43.575 54.503,43.33 54.503,43.086 54.503,42.841 54.503,42.596 54.503,42.352 54.503,42.107 54.503,41.863 54.503,41.618 54.503,41.373 54.503,41.129 54.503,40.884 54.503,40.64 54.503,40.395 54.503,40.15 54.503,39.906 54.503,39.661 54.503,39.416 54.503,39.172 54.503,39.062 54.567,38.997 54.723,38.841 54.741,38.863 54.95,39.072 54.95,55.339 54.827,55.376 54.654,55.469 54.503,55.593 54.379,55.744 54.286,55.917 54.229,56.105 54.21,56.3 54.229,56.495 54.286,56.683 54.379,56.856 54.503,57.007 54.56,57.054 53.32,57.054 53.377,57.007 53.501,56.856 53.594,56.683 53.651,56.495 53.67,56.3 53.651,56.105 53.594,55.917 53.501,55.744 53.377,55.593 53.226,55.469 53.053,55.376 52.865,55.319 52.67,55.3 52.475,55.319 52.287,55.376 52.114,55.469 51.963,55.593 51.839,55.744 51.746,55.917 51.689,56.105 51.67,56.3 51.689,56.495 51.746,56.683 51.839,56.856 51.963,57.007
GND on Bottom (solid): 52.667,45.358 52.674,45.283 52.667,45.205 52.644,45.13 52.607,45.061 52.557,45.001 52.497,44.951 52.456,44.929 52.474,44.931 52.553,44.923 52.628,44.901 52.697,44.864 52.755,44.816 52.852,44.721 52.854,44.719 52.904,44.658 52.941,44.589 52.95,44.558 53.068,44.44 53.283,44.225 53.333,44.165 53.37,44.095 53.392,44.02 53.4,43.942 53.4,43.614 53.4,43.285 53.4,42.957 53.4,42.628 53.4,42.3 53.392,42.222 53.37,42.147 53.333,42.078 53.283,42.017 53.222,41.967 53.153,41.93 53.078,41.908 53,41.9 52.922,41.908 52.847,41.93 52.778,41.967 52.717,42.017 52.667,42.078 52.63,42.147 52.608,42.222 52.6,42.3 52.6,42.628 52.6,42.957 52.6,43.285 52.6,43.614 52.6,43.777 52.503,43.874 52.288,44.088 52.266,44.116 52.422,38.579 52.421,38.579 52.421,38.572 52.422,38.572 52.422,38.535 55.064,35.894 55.078,35.892 55.153,35.87 55.222,35.833 55.283,35.783 55.291,35.773 55.291,36.01 55.291,36.257 55.291,36.503 55.291,36.75 55.291,36.996 55.291,37.243 55.291,37.354 55.226,37.419 55.067,37.579 54.907,37.739 54.747,37.898 54.587,38.058 54.427,38.218 54.268,38.378 54.108,38.538 53.948,38.697 53.908,38.747 53.878,38.803 53.859,38.864 53.853,38.927 53.853,39.172 53.853,39.416 53.853,39.661 53.853,39.906 53.853,40.15 53.853,40.395 53.853,40.64 53.853,40.884 53.853,41.129 53.853,41.373 53.853,41.618 53.853,41.863 53.853,42.107 53.853,42.352 53.853,42.596 53.853,42.841 53.853,43.086 53.853,43.33 53.853,43.575 53.853,43.82 53.853,44.064 53.853,44.174 53.783,44.244 53.618,44.409 53.453,44.574 53.288,44.739 53.123,44.904 52.958,45.069 52.793,45.234 52.671,45.356 52.67,45.356
GND on Bottom (solid): 45.041,32.118 45.035,32.064 45.01,31.98 44.968,31.902 44.933,31.859 45.185,31.912 45.139,31.949 45.089,32.01 45.052,32.079

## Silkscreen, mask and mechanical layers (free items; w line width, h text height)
Top Overlay:
  text "2L • BOTTOM GND POUR" at 38.4,56.9 h0.48
  text "I2C 0x76 • USB-C" at 68.4,56.9 h0.55
  text "BME280" at 71.4,27.05 h0.58
  text "QUICK CONFIGURE • SENSOR" at 57.4,26.9 h0.72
